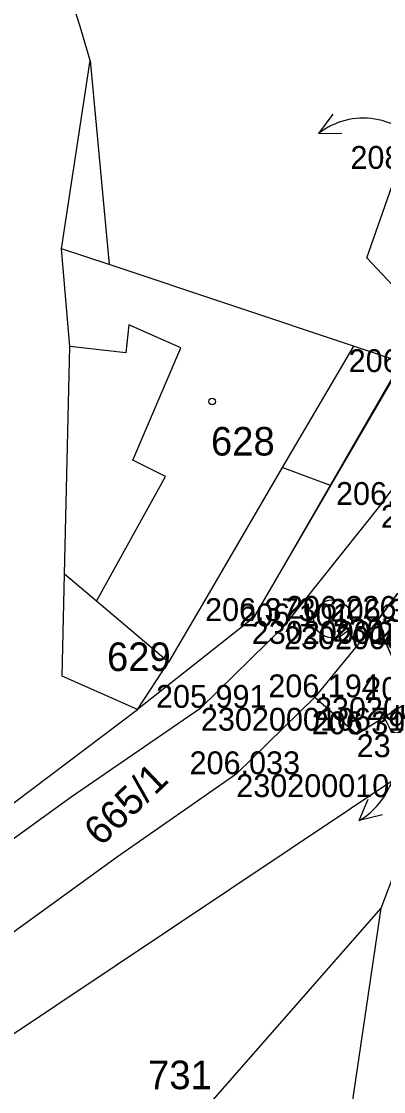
# Model space of a CAD drawing. Extents: x -563148 to -561712, y -1182311 to -1179502.
# Drawn here: x -562591.4 to -562572.4, y -1181075.4 to -1181019.2 of the extents above; entities that cross this region are included whole.
import ezdxf

# ---------------------------------------------------------------- set-up
doc = ezdxf.new("R2010")
doc.units = 0
for name, color, linetype in [('Vrstva 16', 7, 'Continuous'), ('Vrstva 17', 7, 'Continuous'), ('Vrstva 43', 7, 'Continuous'), ('Vrstva 49', 7, 'Continuous'), ('Vrstva 53', 7, 'Continuous'), ('Vrstva 55', 7, 'Continuous'), ('Vrstva 56', 7, 'Continuous'), ('Vrstva 57', 7, 'Continuous'), ('Vrstva 60', 7, 'Continuous'), ('Vrstva 61', 7, 'Continuous')]:
    doc.layers.add(name, color=color, linetype=linetype)

msp = doc.modelspace()

# ---------------------------------------------------------------- linework, layer by layer
at = {"layer": 'Vrstva 16'}
for p, q in [((-562572.73, -1181050.694), (-562570.911, -1181054.802)), ((-562575.954, -1181054.661), (-562573.765, -1181056.605))]:
    msp.add_line(p, q, dxfattribs=at)
msp.add_lwpolyline([(-562581.943, -1181055.215), (-562577.582, -1181050.935), (-562572.493, -1181044.555), (-562569.683, -1181040.729), (-562565.614, -1181035.19), (-562563.691, -1181031.501), (-562558.151, -1181023.673), (-562557.554, -1181025.769), (-562563.649, -1181036.436), (-562565.184, -1181039.097), (-562569.17, -1181045.921), (-562572.73, -1181050.694), (-562575.954, -1181054.661), (-562580.087, -1181058.703)], dxfattribs=at)
at = {"layer": 'Vrstva 17'}
for p, q in [((-562571.733, -1181037.575), (-562579.272, -1181050.655)), ((-562573.765, -1181056.605), (-562570.911, -1181054.802))]:
    msp.add_line(p, q, dxfattribs=at)
for points in [[(-562575.014, -1181024.018), (-562575.763, -1181025.037), (-562574.542, -1181025.031)], [(-562572.409, -1181060.835), (-562573.637, -1181061.138), (-562573.165, -1181060.012)]]:
    msp.add_lwpolyline(points, dxfattribs=at)
for centre, start, end in [((-562573.415, -1181028.069), 34.228, 127.7479), ((-562575.542, -1181057.81), 299.7973, 33.3172)]:
    msp.add_arc(centre, 3.834, start, end, dxfattribs=at)
at = {"layer": 'Vrstva 43'}
msp.add_circle((-562575.025, -1181050.539), 1, dxfattribs=at)
at = {"layer": 'Vrstva 49'}
msp.add_lwpolyline([(-562570.911, -1181054.802), (-562572.73, -1181050.694), (-562569.17, -1181045.921), (-562565.184, -1181039.097), (-562563.649, -1181036.436), (-562557.554, -1181025.769)], dxfattribs=at)
at = {"layer": 'Vrstva 53'}
for p, q in [((-562572.48, -1181065.74), (-562569.31, -1181057.32)), ((-562575.38, -1181085.31), (-562572.48, -1181065.74))]:
    msp.add_line(p, q, dxfattribs=at)
at = {"layer": 'Vrstva 55'}
for p, q in [((-562588.29, -1181019.42), (-562596.77, -1180992.57)), ((-562573.24, -1181031.57), (-562567.8, -1181016.02)), ((-562587.75, -1181021.21), (-562588.29, -1181019.42)), ((-562589.26, -1181031.1), (-562587.75, -1181021.21)), ((-562586.76, -1181031.93), (-562589.26, -1181031.1)), ((-562588.82, -1181036.24), (-562589.26, -1181031.1)), ((-562570.11, -1181034.9), (-562573.24, -1181031.57)), ((-562573.94, -1181036.21), (-562586.76, -1181031.93)), ((-562589.1, -1181048.19), (-562588.82, -1181036.24)), ((-562571.37, -1181037.07), (-562573.94, -1181036.21)), ((-562571.37, -1181037.07), (-562575.14, -1181043.53)), ((-562575.14, -1181043.53), (-562579.19, -1181050.48)), ((-562589.22, -1181053.55), (-562589.1, -1181048.19)), ((-562587.42, -1181049.61), (-562589.1, -1181048.19)), ((-562583.64, -1181052.82), (-562587.42, -1181049.61)), ((-562579.19, -1181050.48), (-562585.28, -1181055.31)), ((-562585.28, -1181055.31), (-562583.64, -1181052.82)), ((-562585.28, -1181055.31), (-562589.22, -1181053.55)), ((-562595.92, -1181063.33), (-562585.28, -1181055.31)), ((-562569.31, -1181057.32), (-562596.19, -1181075.31)), ((-562586.05, -1181081.22), (-562572.48, -1181065.74))]:
    msp.add_line(p, q, dxfattribs=at)
at = {"layer": 'Vrstva 56'}
for p, q in [((-562587.75, -1181021.21), (-562586.76, -1181031.93)), ((-562585.72, -1181035.1), (-562585.89, -1181036.57)), ((-562583, -1181036.3), (-562585.72, -1181035.1)), ((-562585.89, -1181036.57), (-562588.82, -1181036.24)), ((-562585.52, -1181042.2), (-562583, -1181036.3)), ((-562573.94, -1181036.21), (-562577.67, -1181042.59)), ((-562583.8, -1181043.07), (-562585.52, -1181042.2)), ((-562587.42, -1181049.61), (-562583.8, -1181043.07)), ((-562577.67, -1181042.59), (-562581.87, -1181049.8)), ((-562575.14, -1181043.53), (-562577.67, -1181042.59)), ((-562581.87, -1181049.8), (-562583.64, -1181052.82)), ((-562588.76, -1181059.89), (-562581.943, -1181055.215)), ((-562580.087, -1181058.703), (-562586.32, -1181063.05)), ((-562609.58, -1181074.94), (-562588.76, -1181059.89)), ((-562586.32, -1181063.05), (-562607.2, -1181078.16))]:
    msp.add_line(p, q, dxfattribs=at)
at = {"layer": 'Vrstva 57'}
msp.add_circle((-562581.35, -1181039.12), 0.175, dxfattribs=at)
at = {"layer": 'Vrstva 60'}
for p, q in [((-562572.493, -1181044.555), (-562572.493, -1181044.555)), ((-562579.272, -1181050.655), (-562579.272, -1181050.655)), ((-562577.582, -1181050.935), (-562577.582, -1181050.935)), ((-562575.025, -1181050.539), (-562575.025, -1181050.539)), ((-562572.73, -1181050.694), (-562572.73, -1181050.694)), ((-562575.954, -1181054.661), (-562575.954, -1181054.661)), ((-562581.943, -1181055.215), (-562581.943, -1181055.215)), ((-562573.765, -1181056.605), (-562573.765, -1181056.605)), ((-562580.087, -1181058.703), (-562580.087, -1181058.703))]:
    msp.add_line(p, q, dxfattribs=at)

# ---------------------------------------------------------------- texts
at = {"layer": 'Vrstva 57'}
for s, p in [('628', (-562581.414, -1181041.96)), ('629', (-562586.874, -1181053.28)), ('731', (-562584.717, -1181075.25))]:
    msp.add_text(s, height=1.5, dxfattribs=at).set_placement(p)
msp.add_text('665/1', height=1.5, rotation=43.6033, dxfattribs=at).set_placement((-562587.198, -1181062.541))
at = {"layer": 'Vrstva 60'}
for s, p in [('230200010669', (-562572.493, -1181045.755)), ('230200010679', (-562579.272, -1181051.855)), ('230200010670', (-562577.582, -1181052.135)), ('230200010676', (-562575.025, -1181051.739)), ('230200010674', (-562572.73, -1181051.894)), ('230200010673', (-562575.954, -1181055.861)), ('230200010671', (-562581.943, -1181056.415)), ('230200010677', (-562573.765, -1181057.805)), ('230200010672', (-562580.087, -1181059.903))]:
    msp.add_text(s, height=1.2, dxfattribs=at).set_placement(p)
at = {"layer": 'Vrstva 61'}
for s, p in [('208.588', (-562574.093, -1181026.898)), ('206.908', (-562574.187, -1181037.575)), ('206.431', (-562574.85, -1181044.555)), ('206.373', (-562581.724, -1181050.655)), ('206.101', (-562579.939, -1181050.935)), ('206.226', (-562577.477, -1181050.539)), ('206.327', (-562575.182, -1181050.694)), ('206.194', (-562578.405, -1181054.661)), ('206.496', (-562573.363, -1181054.802)), ('205.991', (-562584.3, -1181055.215)), ('206.391', (-562576.122, -1181056.605)), ('206.033', (-562582.539, -1181058.703))]:
    msp.add_text(s, height=1.2, dxfattribs=at).set_placement(p)

doc.saveas('drawing.dxf')
